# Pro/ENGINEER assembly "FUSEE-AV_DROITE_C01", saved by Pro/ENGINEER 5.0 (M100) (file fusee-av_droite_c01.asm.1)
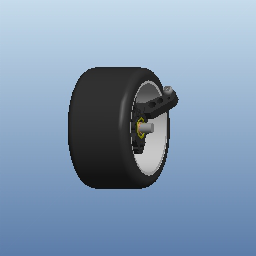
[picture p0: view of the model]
Units: millimeter Newton Second (mmNs); MM, TONNE, HOURS

Other components: 80657500-FUSEE_AV_DEPORT_C01, ECROU_HFR_M6, ENTRETOISE_8X13_C01, 80351300-AXE_ROUE_AV_LONG_C01, VIS_CHC_M-4X16, RONDELLE_PLATE-D6, E-ROTULE_VIS_C02, ROULEMENT_BC_8X22X7, 80655614-CARRE_ROUE_14_C01, ECROU_SPHER-M15, ROULEMENT_BC_8X22X7, 80650400-LEVIER_FUSEE_AV_C01, ROUE_V0_C01, ECROU_SPHER-M15

Other named items: A-DROITE, A-DESSUS, A-FACE, A-R0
